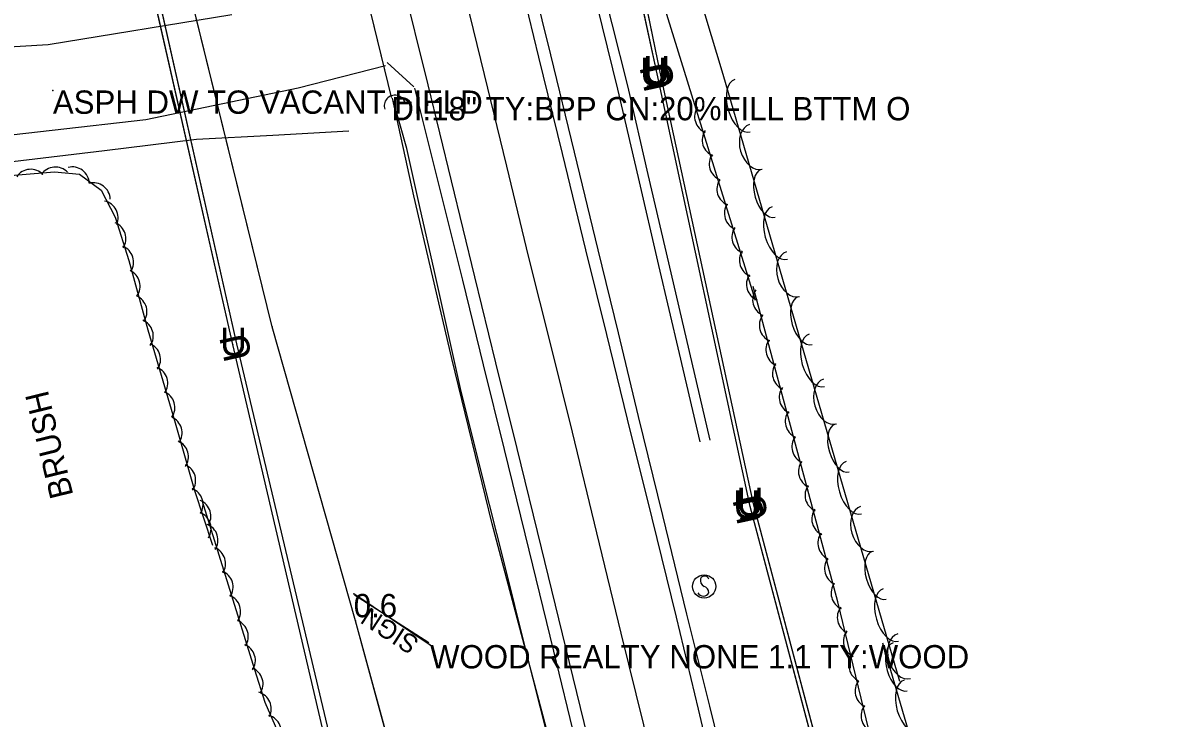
# Model space of a CAD drawing. Extents: x 954793 to 988390, y 1867850 to 1924428.
# Drawn here: x 960688.2 to 960932.4, y 1908587.1 to 1908736.2 of the extents above; entities that cross this region are included whole.
import ezdxf

# ---------------------------------------------------------------- set-up
doc = ezdxf.new("R2010")
doc.units = 0
for name, color, linetype in [('Default', 7, 'Continuous'), ('S_CROSS_DRAIN', 7, 'Continuous'), ('S_DITCHLINE', 7, 'Continuous'), ('S_DRG_PT_SYM', 7, 'Continuous'), ('S_DRIVEWAY', 7, 'Continuous'), ('S_EDGE_PAVEMENT', 7, 'Continuous'), ('S_FIBER_OPTIC_CABLE', 7, 'Continuous'), ('S_MSC_PT_SYM', 7, 'Continuous'), ('S_PAVEMENT_CROWN', 7, 'Continuous'), ('S_SHOULDER', 7, 'Continuous'), ('S_SIDE_DRAIN', 7, 'Continuous'), ('S_SIDE_DRAIN_ANNOT', 7, 'Continuous'), ('S_SIGN', 7, 'Continuous'), ('S_SIGN_ANNOT', 7, 'Continuous'), ('S_STREAM', 7, 'Continuous'), ('S_SURVEY_TEXT_ANNOT', 7, 'Continuous'), ('S_TREE', 7, 'Continuous'), ('S_TREE_ANNOT', 7, 'Continuous'), ('S_UNDERGROUND_CABLE', 7, 'Continuous'), ('S_UTL_PT_SYM', 7, 'Continuous'), ('S_WATER_UTILITIES', 7, 'Continuous')]:
    doc.layers.add(name, color=color, linetype=linetype)

msp = doc.modelspace()

# ---------------------------------------------------------------- linework, layer by layer
at = {"layer": 'S_CROSS_DRAIN'}
msp.add_arc((960767.94, 1908718.4), 2.3, 18.0625, 198.3917, dxfattribs=at)
at = {"layer": 'S_DITCHLINE'}
for points in [[(960835.47, 1908646.75), (960831.06, 1908665.74), (960826.66, 1908684.73), (960822.25, 1908703.72), (960817.85, 1908722.71), (960814.51, 1908736.01), (960811.16, 1908749.31)], [(960833.33, 1908646.42), (960828.93, 1908665.31), (960824.52, 1908684.2), (960820.12, 1908703.09), (960815.71, 1908721.98), (960812.44, 1908735.34), (960809.17, 1908748.7)], [(960800.69, 1908583.14), (960796.01, 1908601.82), (960791.34, 1908620.49), (960786.66, 1908639.17), (960781.99, 1908657.85), (960779.12, 1908670.7), (960776.26, 1908683.56), (960773.39, 1908696.41), (960770.52, 1908709.26), (960767.67, 1908719.33)], [(960758.1, 1908712.97), (960741.75, 1908712.07), (960725.4, 1908711.17), (960705.71, 1908708.8), (960686.02, 1908706.42), (960669.96, 1908705.21), (960653.9, 1908704)]]:
    msp.add_lwpolyline(points, dxfattribs=at)
at = {"layer": 'S_DRG_PT_SYM'}
msp.add_lwpolyline([(960767.18, 1908720.31), (960767.13, 1908720.3), (960767.18, 1908720.31), (960767.19, 1908720.26), (960767.18, 1908720.31), (960767.22, 1908720.32), (960767.18, 1908720.31), (960767.16, 1908720.36)], close=True, dxfattribs=at)
msp.add_lwpolyline([(960767.18, 1908720.31), (960767.13, 1908720.3), (960767.18, 1908720.31), (960767.19, 1908720.26), (960767.18, 1908720.31), (960767.22, 1908720.32), (960767.18, 1908720.31), (960767.16, 1908720.36)], close=True, dxfattribs=at)
msp.add_lwpolyline([(960767.18, 1908720.31), (960767.18, 1908720.36), (960767.18, 1908720.31), (960767.13, 1908720.31), (960767.18, 1908720.31), (960767.18, 1908720.26), (960767.18, 1908720.31), (960767.23, 1908720.31)], dxfattribs=at)
at = {"layer": 'S_DRIVEWAY'}
for points in [[(960732.98, 1908737.94), (960693.66, 1908731.46), (960655.1, 1908729.23)], [(960772.02, 1908722.51), (960766.31, 1908727.68)], [(960674.33, 1908710.95), (960714.54, 1908715.52), (960747.18, 1908722.26), (960765.93, 1908727.03)]]:
    msp.add_lwpolyline(points, dxfattribs=at)
at = {"layer": 'S_EDGE_PAVEMENT'}
for points in [[(960905.85, 1908307.8), (960899.95, 1908328.37), (960894.05, 1908349.52), (960888.14, 1908370.66), (960882.97, 1908389.61), (960877.81, 1908408.56), (960873.24, 1908426.32), (960868.67, 1908444.08), (960862.82, 1908467.58), (960856.97, 1908491.09), (960852.21, 1908510.36), (960847.45, 1908529.62), (960842.57, 1908549.5), (960837.68, 1908569.38), (960832.97, 1908589.07), (960828.26, 1908608.77), (960823.04, 1908630), (960817.81, 1908651.23), (960813.33, 1908669.4), (960808.85, 1908687.57), (960803.83, 1908708.22), (960798.81, 1908728.88), (960793.43, 1908751.09)], [(960882.58, 1908300.08), (960876.3, 1908321.43), (960870.35, 1908342.62), (960864.39, 1908363.81), (960859.29, 1908383), (960854.2, 1908402.18), (960849.51, 1908420.39), (960844.83, 1908438.59), (960838.99, 1908461.91), (960833.16, 1908485.24), (960828.48, 1908504.33), (960823.81, 1908523.42), (960818.93, 1908543.56), (960814.06, 1908563.7), (960809.3, 1908582.99), (960804.55, 1908602.29), (960799.33, 1908623.63), (960794.11, 1908644.97), (960789.58, 1908663.35), (960785.05, 1908681.73), (960780.05, 1908702.34), (960775.05, 1908722.94), (960769.46, 1908745.75)]]:
    msp.add_lwpolyline(points, dxfattribs=at)
at = {"layer": 'S_FIBER_OPTIC_CABLE'}
for p, q in [((960733.23, 1908667.22), (960715.56, 1908745.03)), ((960752.95, 1908582.87), (960733.23, 1908667.22))]:
    msp.add_line(p, q, dxfattribs=at)
msp.add_lwpolyline([(960823.74, 1908306.68), (960802.22, 1908384.11), (960790.78, 1908429.58), (960771.11, 1908509.31), (960752.95, 1908582.87), (960733.23, 1908667.22), (960715.56, 1908745.03), (960697.63, 1908827.49), (960680.37, 1908913.63), (960662.22, 1908992.74), (960644.98, 1909068.04), (960624.13, 1909159.31), (960611.12, 1909197.71), (960608.8, 1909220.01), (960584.66, 1909279.06), (960520.73, 1909366.93), (960487.68, 1909419.99)], dxfattribs=at)
msp.add_lwpolyline([(960823.74, 1908306.68), (960802.22, 1908384.11), (960790.78, 1908429.58), (960771.11, 1908509.31), (960752.95, 1908582.87), (960733.23, 1908667.22), (960715.56, 1908745.03), (960697.63, 1908827.49), (960680.37, 1908913.63), (960662.22, 1908992.74), (960644.98, 1909068.04), (960624.13, 1909159.31), (960611.12, 1909197.71), (960608.8, 1909220.01), (960584.66, 1909279.06), (960520.73, 1909366.93), (960487.68, 1909419.99)], dxfattribs=at)
at = {"layer": 'S_MSC_PT_SYM'}
for points in [[(960694.64, 1908721.71), (960694.64, 1908721.76), (960694.64, 1908721.71), (960694.59, 1908721.71), (960694.64, 1908721.71), (960694.64, 1908721.66), (960694.64, 1908721.71), (960694.69, 1908721.71)], [(960694.64, 1908721.71), (960694.64, 1908721.76), (960694.64, 1908721.71), (960694.59, 1908721.71), (960694.64, 1908721.71), (960694.64, 1908721.66), (960694.64, 1908721.71), (960694.69, 1908721.71)], [(960759.12, 1908613.78), (960759.09, 1908613.74), (960759.12, 1908613.78), (960759.16, 1908613.75), (960759.12, 1908613.78), (960759.15, 1908613.82), (960759.12, 1908613.78), (960759.08, 1908613.81)], [(960759.12, 1908613.78), (960759.09, 1908613.74), (960759.12, 1908613.78), (960759.16, 1908613.75), (960759.12, 1908613.78), (960759.15, 1908613.82), (960759.12, 1908613.78), (960759.08, 1908613.81)], [(960775.48, 1908602.82), (960775.45, 1908602.78), (960775.48, 1908602.82), (960775.52, 1908602.79), (960775.48, 1908602.82), (960775.51, 1908602.86), (960775.48, 1908602.82), (960775.44, 1908602.85)], [(960775.48, 1908602.82), (960775.45, 1908602.78), (960775.48, 1908602.82), (960775.52, 1908602.79), (960775.48, 1908602.82), (960775.51, 1908602.86), (960775.48, 1908602.82), (960775.44, 1908602.85)]]:
    msp.add_lwpolyline(points, close=True, dxfattribs=at)
for points in [[(960694.64, 1908721.71), (960694.64, 1908721.76), (960694.64, 1908721.71), (960694.59, 1908721.71), (960694.64, 1908721.71), (960694.64, 1908721.66), (960694.64, 1908721.71), (960694.69, 1908721.71)], [(960759.12, 1908613.78), (960759.12, 1908613.83), (960759.12, 1908613.78), (960759.07, 1908613.78), (960759.12, 1908613.78), (960759.12, 1908613.73), (960759.12, 1908613.78), (960759.17, 1908613.78)], [(960775.48, 1908602.82), (960775.48, 1908602.87), (960775.48, 1908602.82), (960775.43, 1908602.82), (960775.48, 1908602.82), (960775.48, 1908602.77), (960775.48, 1908602.82), (960775.53, 1908602.82)]]:
    msp.add_lwpolyline(points, dxfattribs=at)
at = {"layer": 'S_PAVEMENT_CROWN'}
msp.add_lwpolyline([(960894.26, 1908303.84), (960888.03, 1908325.24), (960882.18, 1908346.14), (960876.34, 1908367.05), (960871.19, 1908385.93), (960866.04, 1908404.81), (960861.32, 1908423.04), (960856.6, 1908441.26), (960850.74, 1908464.78), (960844.88, 1908488.29), (960840.35, 1908507.53), (960835.82, 1908526.78), (960830.99, 1908546.41), (960826.16, 1908566.04), (960821.3, 1908585.7), (960816.45, 1908605.37), (960811.24, 1908626.91), (960806.03, 1908648.46), (960801.35, 1908667.19), (960796.66, 1908685.93), (960791.9, 1908705.52), (960787.15, 1908725.1), (960781.56, 1908748.02)], dxfattribs=at)
at = {"layer": 'S_SHOULDER'}
for points in [[(960908.38, 1908304.85), (960905.28, 1908315.69), (960901.51, 1908328.88), (960895.75, 1908349.92), (960890, 1908370.97), (960884.91, 1908390.03), (960879.83, 1908409.08), (960875.22, 1908426.81), (960870.61, 1908444.54), (960864.86, 1908468.08), (960859.12, 1908491.63), (960854.36, 1908510.81), (960849.59, 1908530), (960844.94, 1908549.98), (960840.29, 1908569.96), (960835.41, 1908589.69), (960830.52, 1908609.41), (960825.35, 1908630.63), (960820.18, 1908651.85), (960815.83, 1908669.72), (960811.48, 1908687.58), (960806.43, 1908708.45), (960801.37, 1908729.32), (960795.83, 1908751.67)], [(960878.52, 1908299.82), (960872.51, 1908320.55), (960866.76, 1908342.01), (960861.02, 1908363.47), (960855.97, 1908382.82), (960850.93, 1908402.16), (960846.37, 1908419.96), (960841.81, 1908437.76), (960836.11, 1908461.04), (960830.42, 1908484.32), (960825.7, 1908503.57), (960820.99, 1908522.82), (960816.11, 1908543.02), (960811.24, 1908563.23), (960806.61, 1908582.38), (960801.98, 1908601.53), (960796.71, 1908623.15), (960791.44, 1908644.76), (960786.96, 1908662.91), (960782.48, 1908681.05), (960777.34, 1908701.64), (960772.2, 1908722.22)]]:
    msp.add_lwpolyline(points, dxfattribs=at)
at = {"layer": 'S_SIDE_DRAIN'}
msp.add_line((960767.18, 1908720.31), (960757.75, 1908759), dxfattribs=at)
msp.add_lwpolyline([(960767.18, 1908720.31), (960757.75, 1908759)], dxfattribs=at)
msp.add_lwpolyline([(960767.18, 1908720.31), (960757.75, 1908759)], dxfattribs=at)
at = {"layer": 'S_SIGN'}
for p, q in [((960775.48, 1908602.82), (960759.12, 1908613.78)), ((960775.19, 1908603.31), (960759.3, 1908613.52))]:
    msp.add_line(p, q, dxfattribs=at)
msp.add_lwpolyline([(960775.48, 1908602.82), (960759.12, 1908613.78)], dxfattribs=at)
msp.add_lwpolyline([(960775.48, 1908602.82), (960759.12, 1908613.78)], dxfattribs=at)
msp.add_circle((960834.22, 1908615.4), 2.49, dxfattribs=at)
for centre, radius, start, end in [((960834.29, 1908616.67), 0.95, 16.5258, 156.8957), ((960834.9, 1908616.73), 1.5, 167.1196, 241.9813), ((960833.8, 1908614.06), 1.4, 358.6529, 73.7063), ((960834.06, 1908614.58), 1.28, 204.641, 335.359)]:
    msp.add_arc(centre, radius, start, end, dxfattribs=at)
at = {"layer": 'S_STREAM'}
msp.add_lwpolyline([(960801.01, 1908582.7), (960788.79, 1908628.8), (960780.12, 1908664.24), (960772.02, 1908699.09), (960767.41, 1908720.05)], dxfattribs=at)
at = {"layer": 'S_TREE'}
for points in [[(960876.17, 1908595.02), (960838.3, 1908725.17), (960822.84, 1908776.34), (960801.4, 1908874.11), (960795.09, 1908889.32), (960787.82, 1908910.68), (960780.03, 1908934.49), (960776.6, 1908949.06), (960776.25, 1908964.36), (960773.11, 1908981.47), (960765.82, 1909011.35), (960762.84, 1909047.83), (960759.92, 1909061.45), (960754.93, 1909070.28), (960749.14, 1909079.25), (960745.14, 1909092.47), (960741.6, 1909105.05), (960739.51, 1909114.48)], [(960845.22, 1908676.68), (960822.08, 1908751.46), (960819.15, 1908765.26), (960817.65, 1908780.1), (960816.1, 1908790.64), (960810.94, 1908811.92), (960797.11, 1908866.19)], [(960571.65, 1908725.05), (960604.47, 1908711.21), (960626.23, 1908707.47), (960655.09, 1908703.48), (960677.81, 1908702.76), (960687.19, 1908703.61), (960694.98, 1908704.28), (960700.35, 1908703.8), (960704.99, 1908700.34), (960708.01, 1908694.54), (960710.93, 1908685.25), (960714.99, 1908670.37), (960720.7, 1908650.98), (960724.99, 1908635.93), (960728.82, 1908624.25)], [(960923.53, 1908428.18), (960916.05, 1908429.6), (960906.66, 1908431.21), (960901.88, 1908434.22), (960894.24, 1908450.32), (960886.48, 1908477.06), (960884.75, 1908493.84), (960887.01, 1908503.65), (960884.96, 1908520.94), (960862.84, 1908612.1), (960844.73, 1908679.69)], [(960726.56, 1908633.91), (960737.87, 1908597.61), (960740.05, 1908590.58), (960747, 1908574.69), (960758.29, 1908568.33), (960774.36, 1908564.57), (960794.69, 1908558.2), (960800.69, 1908554.75)], [(960958.19, 1908305.08), (960946.97, 1908339.49), (960940.87, 1908358.17), (960931.2, 1908388.1), (960924.28, 1908410.43), (960919.97, 1908424.61), (960924.21, 1908437.71), (960935.94, 1908446.3), (960948.02, 1908452.53), (960961.28, 1908477.82), (960959.13, 1908486.15), (960956.78, 1908490.08), (960955.55, 1908490.73), (960945.19, 1908493.98), (960932.72, 1908496.62), (960916.49, 1908503.66), (960903.79, 1908516.55), (960893.92, 1908531.65), (960886.44, 1908555.64), (960872.51, 1908603.23)]]:
    msp.add_lwpolyline(points, dxfattribs=at)
for centre, start, end in [((960835.81, 1908716.11), 146.3972, 247.9941), ((960837.44, 1908711.09), 146.3972, 247.9941), ((960838.94, 1908705.97), 146.3972, 247.9941), ((960698.8, 1908701.68), 2.4174, 104.0143), ((960689.9, 1908701.17), 44.1187, 145.7156), ((960695.18, 1908701.66), 44.1187, 145.7156), ((960703.3, 1908698.27), 2.4174, 104.0143), ((960840.58, 1908700.57), 146.3972, 247.9941), ((960704.98, 1908694.44), 336.7249, 78.3219), ((960842.19, 1908695.37), 146.3972, 247.9941), ((960706.66, 1908689.96), 326.6616, 68.2585), ((960843.79, 1908690.31), 146.3972, 247.9941), ((960708.29, 1908684.91), 326.6616, 68.2585), ((960845.42, 1908685.29), 146.3972, 247.9941), ((960709.7, 1908679.76), 324.4624, 66.0593), ((960846.93, 1908680.17), 146.3972, 247.9941), ((960848.25, 1908676.85), 144.2017, 245.7986), ((960711.16, 1908674.3), 324.4624, 66.0593), ((960712.52, 1908669.09), 325.6106, 67.2075), ((960849.68, 1908671.39), 144.2017, 245.7986), ((960714.08, 1908664.04), 325.6106, 67.2075), ((960851.08, 1908666.13), 144.2017, 245.7986), ((960715.61, 1908658.96), 325.6106, 67.2075), ((960852.49, 1908661.02), 144.2017, 245.7986), ((960717.15, 1908653.74), 325.6106, 67.2075), ((960853.93, 1908655.93), 144.2017, 245.7986), ((960718.69, 1908648.33), 325.1135, 66.7104), ((960855.24, 1908650.76), 144.2017, 245.7986), ((960856.67, 1908645.3), 144.2017, 245.7986), ((960720.08, 1908643.18), 325.1135, 66.7104), ((960858.07, 1908640.04), 144.2017, 245.7986), ((960721.6, 1908638.12), 325.1135, 66.7104), ((960859.48, 1908634.93), 144.2017, 245.7986), ((960723.2, 1908632.96), 327.3632, 68.9601), ((960724.86, 1908630.43), 326.501, 68.0979), ((960724.9, 1908627.79), 327.3632, 68.9601), ((960860.92, 1908629.84), 144.2017, 245.7986), ((960726.38, 1908625.31), 326.501, 68.0979), ((960862.23, 1908624.67), 144.2017, 245.7986), ((960728.02, 1908620.29), 326.501, 68.0979), ((960863.66, 1908619.21), 144.2017, 245.7986), ((960729.63, 1908615.24), 326.501, 68.0979), ((960865.06, 1908613.95), 144.2017, 245.7986), ((960731.24, 1908610.04), 326.501, 68.0979), ((960866.39, 1908608.75), 142.8368, 244.4337), ((960732.89, 1908604.64), 326.501, 68.0979), ((960867.71, 1908603.64), 142.8368, 244.4337), ((960734.41, 1908599.52), 326.501, 68.0979), ((960868.89, 1908598.43), 142.8368, 244.4337), ((960736.05, 1908594.5), 326.4774, 68.0743), ((960870.19, 1908592.94), 142.8368, 244.4337), ((960737.8, 1908589.19), 332.8134, 74.4103), ((960871.47, 1908587.65), 142.8368, 244.4337), ((960739.97, 1908584.2), 332.8134, 74.4103)]:
    msp.add_arc(centre, 3.64, start, end, dxfattribs=at)
for centre, major_axis, ratio in [((960842.46, 1908718.45), (1.64, -5.63), 0.55008), ((960845.3, 1908709.63), (1.38, -4.76), 0.685311), ((960847.93, 1908699.66), (1.49, -5.13), 0.540699), ((960850.41, 1908691.15), (1.64, -5.63), 0.55008), ((960853.24, 1908682.33), (1.38, -4.76), 0.685311), ((960855.87, 1908672.37), (1.49, -5.13), 0.540699), ((960858.35, 1908663.85), (1.64, -5.63), 0.55008), ((960861.19, 1908655.03), (1.38, -4.76), 0.685311), ((960863.82, 1908645.07), (1.49, -5.13), 0.540699), ((960866.29, 1908636.55), (1.64, -5.63), 0.55008), ((960869.13, 1908627.74), (1.38, -4.76), 0.685311), ((960871.76, 1908617.77), (1.49, -5.13), 0.540699), ((960874.24, 1908609.26), (1.64, -5.63), 0.55008), ((960877.08, 1908600.44), (1.38, -4.76), 0.685311), ((960876.21, 1908598.16), (1.5, -5.13), 0.540699), ((960878.7, 1908589.65), (1.65, -5.63), 0.55008)]:
    msp.add_ellipse(centre, major_axis=major_axis, ratio=ratio, start_param=3.141593, end_param=6.283185, dxfattribs=at)
at = {"layer": 'S_UNDERGROUND_CABLE'}
for p, q in [((960824.14, 1908725.3), (960808.48, 1908797.9)), ((960824.78, 1908725.66), (960810.01, 1908797.62)), ((960734.09, 1908667.42), (960716.61, 1908744.97)), ((960844.08, 1908632.56), (960824.14, 1908725.3)), ((960844.78, 1908633.08), (960824.78, 1908725.66)), ((960754.11, 1908582.75), (960734.09, 1908667.42)), ((960868.22, 1908541.61), (960844.08, 1908632.56)), ((960869.02, 1908541.86), (960844.78, 1908633.08))]:
    msp.add_line(p, q, dxfattribs=at)
for points in [[(960924.47, 1908058.47), (960931.11, 1908064.94), (960909.84, 1908124.82), (960893, 1908180.71), (960870.95, 1908252.27), (960855.38, 1908288.78), (960824.66, 1908307.36), (960801.48, 1908384.93), (960790.3, 1908429.37), (960771.93, 1908510.1), (960754.11, 1908582.75), (960734.09, 1908667.42), (960716.61, 1908744.97), (960698.42, 1908828.21), (960681.52, 1908913.94), (960663.18, 1908993.44), (960645.91, 1909068.19), (960624.8, 1909158.96), (960612.33, 1909198.29), (960609.74, 1909220.21), (960585.48, 1909279.43), (960521.44, 1909367.02), (960488.5, 1909420.49)], [(960924.47, 1908058.47), (960931.11, 1908064.94), (960909.84, 1908124.82), (960893, 1908180.71), (960870.95, 1908252.27), (960855.38, 1908288.78), (960824.66, 1908307.36), (960801.48, 1908384.93), (960790.3, 1908429.37), (960771.93, 1908510.1), (960754.11, 1908582.75), (960734.09, 1908667.42), (960716.61, 1908744.97), (960698.42, 1908828.21), (960681.52, 1908913.94), (960663.18, 1908993.44), (960645.91, 1909068.19), (960624.8, 1909158.96), (960612.33, 1909198.29), (960609.74, 1909220.21), (960585.48, 1909279.43), (960521.44, 1909367.02), (960488.5, 1909420.49)], [(960945.64, 1908302.15), (960913.02, 1908369.52), (960888.88, 1908455.84), (960868.22, 1908541.61), (960844.08, 1908632.56), (960824.14, 1908725.3), (960808.48, 1908797.9), (960788.35, 1908883.09), (960766.42, 1908964.38), (960745.02, 1909034.36), (960738.49, 1909058.96), (960737.77, 1909085.45), (960735.34, 1909104.37), (960736.79, 1909113.35), (960738.52, 1909122.62), (960729.67, 1909140.01), (960718.57, 1909158.78), (960700.61, 1909211.39), (960677.76, 1909284.06), (960656.04, 1909306.18), (960624.97, 1909341.03), (960589.63, 1909398.18)], [(960945.64, 1908302.15), (960913.02, 1908369.52), (960888.88, 1908455.84), (960868.22, 1908541.61), (960844.08, 1908632.56), (960824.14, 1908725.3), (960808.48, 1908797.9), (960788.35, 1908883.09), (960766.42, 1908964.38), (960745.02, 1909034.36), (960738.49, 1909058.96), (960737.77, 1909085.45), (960735.34, 1909104.37), (960736.79, 1909113.35), (960738.52, 1909122.62), (960729.67, 1909140.01), (960718.57, 1909158.78), (960700.61, 1909211.39), (960677.76, 1909284.06), (960656.04, 1909306.18), (960624.97, 1909341.03), (960589.63, 1909398.18)], [(961060.21, 1908175.08), (961039.44, 1908233.41), (961027.23, 1908256.63), (961018.7, 1908265.88), (960974.34, 1908275.37), (960946.09, 1908302.18), (960913.45, 1908369.8), (960889.73, 1908455.91), (960869.02, 1908541.86), (960844.78, 1908633.08), (960824.78, 1908725.66), (960810.01, 1908797.62), (960789.06, 1908883.36), (960767.15, 1908964.86), (960745.85, 1909034.68), (960739.57, 1909059.72), (960738.76, 1909085.67), (960736.17, 1909104.53), (960737.6, 1909112.95)], [(961060.21, 1908175.08), (961039.44, 1908233.41), (961027.23, 1908256.63), (961018.7, 1908265.88), (960974.34, 1908275.37), (960946.09, 1908302.18), (960913.45, 1908369.8), (960889.73, 1908455.91), (960869.02, 1908541.86), (960844.78, 1908633.08), (960824.78, 1908725.66), (960810.01, 1908797.62), (960789.06, 1908883.36), (960767.15, 1908964.86), (960745.85, 1909034.68), (960739.57, 1909059.72), (960738.76, 1909085.67), (960736.17, 1909104.53), (960737.6, 1909112.95)]]:
    msp.add_lwpolyline(points, dxfattribs=at)
at = {"layer": 'S_UTL_PT_SYM'}
for points in [[(960741.64, 1908671.05), (960741.64, 1908671.1), (960741.64, 1908671.05), (960741.59, 1908671.05), (960741.64, 1908671.05), (960741.64, 1908671), (960741.64, 1908671.05), (960741.69, 1908671.05)], [(960733.23, 1908667.22), (960733.23, 1908667.27), (960733.23, 1908667.22), (960733.18, 1908667.22), (960733.23, 1908667.22), (960733.23, 1908667.17), (960733.23, 1908667.22), (960733.28, 1908667.22)], [(960759.53, 1908608.03), (960759.53, 1908608.08), (960759.53, 1908608.03), (960759.48, 1908608.03), (960759.53, 1908608.03), (960759.53, 1908607.98), (960759.53, 1908608.03), (960759.58, 1908608.03)]]:
    msp.add_lwpolyline(points, dxfattribs=at)
for points in [[(960741.64, 1908671.05), (960741.6, 1908671.04), (960741.64, 1908671.05), (960741.66, 1908671), (960741.64, 1908671.05), (960741.69, 1908671.06), (960741.64, 1908671.05), (960741.63, 1908671.1)], [(960741.64, 1908671.05), (960741.6, 1908671.04), (960741.64, 1908671.05), (960741.66, 1908671), (960741.64, 1908671.05), (960741.69, 1908671.06), (960741.64, 1908671.05), (960741.63, 1908671.1)], [(960733.23, 1908667.22), (960733.18, 1908667.21), (960733.23, 1908667.22), (960733.24, 1908667.17), (960733.23, 1908667.22), (960733.28, 1908667.23), (960733.23, 1908667.22), (960733.22, 1908667.27)], [(960733.23, 1908667.22), (960733.18, 1908667.21), (960733.23, 1908667.22), (960733.24, 1908667.17), (960733.23, 1908667.22), (960733.28, 1908667.23), (960733.23, 1908667.22), (960733.22, 1908667.27)], [(960759.53, 1908608.03), (960759.48, 1908608.02), (960759.53, 1908608.03), (960759.55, 1908607.98), (960759.53, 1908608.03), (960759.58, 1908608.04), (960759.53, 1908608.03), (960759.52, 1908608.08)], [(960759.53, 1908608.03), (960759.48, 1908608.02), (960759.53, 1908608.03), (960759.55, 1908607.98), (960759.53, 1908608.03), (960759.58, 1908608.04), (960759.53, 1908608.03), (960759.52, 1908608.08)]]:
    msp.add_lwpolyline(points, close=True, dxfattribs=at)
at = {"layer": 'S_WATER_UTILITIES'}
for p, q in [((960741.64, 1908671.05), (960721.86, 1908751.64)), ((960759.53, 1908608.03), (960741.64, 1908671.05)), ((960769.86, 1908569.95), (960759.53, 1908608.03))]:
    msp.add_line(p, q, dxfattribs=at)
msp.add_lwpolyline([(960837.31, 1908300.18), (960815.42, 1908376.37), (960799.36, 1908451.13), (960782.06, 1908511.66), (960769.86, 1908569.95), (960759.53, 1908608.03), (960741.64, 1908671.05), (960721.86, 1908751.64), (960703.62, 1908845.92), (960689.57, 1908910.47), (960670.06, 1908999.92), (960653.03, 1909080.98), (960637.25, 1909157.1), (960625.64, 1909197.43), (960610.54, 1909237.02), (960587.29, 1909281.55), (960572.88, 1909303.82), (960526.35, 1909376.08)], dxfattribs=at)
msp.add_lwpolyline([(960837.31, 1908300.18), (960815.42, 1908376.37), (960799.36, 1908451.13), (960782.06, 1908511.66), (960769.86, 1908569.95), (960759.53, 1908608.03), (960741.64, 1908671.05), (960721.86, 1908751.64), (960703.62, 1908845.92), (960689.57, 1908910.47), (960670.06, 1908999.92), (960653.03, 1909080.98), (960637.25, 1909157.1), (960625.64, 1909197.43), (960610.54, 1909237.02), (960587.29, 1909281.55), (960572.88, 1909303.82), (960526.35, 1909376.08)], dxfattribs=at)

# ---------------------------------------------------------------- texts
at = {"layer": 'Default'}
for rotation, p in [(101.6038, (960828.01, 1908722.62)), (360, (960820.51, 1908722.75)), (360, (960821.16, 1908723.12)), (102.175, (960827.4, 1908722.29)), (102.7024, (960737.37, 1908664.44)), (360, (960730.46, 1908664.88)), (360, (960840.45, 1908630.01)), (102.1894, (960848.04, 1908630.07)), (360, (960841.15, 1908630.54)), (102.1346, (960847.33, 1908629.55))]:
    msp.add_text('U', height=6, rotation=rotation, dxfattribs=at).set_placement(p)
at = {"layer": 'S_SIDE_DRAIN_ANNOT'}
msp.add_text('DI:18" TY:BPP CN:20%FILL BTTM O', height=5, dxfattribs=at).set_placement((960767.18, 1908715.31))
at = {"layer": 'S_SIGN_ANNOT'}
for s, p in [('0.6', (960759.12, 1908608.78)), ('WOOD REALTY NONE 1.1 TY:WOOD', (960775.48, 1908597.82))]:
    msp.add_text(s, height=5, dxfattribs=at).set_placement(p)
msp.add_text('SIGN', height=4, rotation=146.9771, dxfattribs=at).set_placement((960773.41, 1908603.97))
at = {"layer": 'S_SURVEY_TEXT_ANNOT'}
msp.add_text('ASPH DW TO VACANT FIELD', height=5, dxfattribs=at).set_placement((960694.64, 1908716.71))
at = {"layer": 'S_TREE_ANNOT'}
msp.add_text('BRUSH', height=5, rotation=103.759, dxfattribs=at).set_placement((960699.06, 1908634.95))

doc.saveas('drawing.dxf')
